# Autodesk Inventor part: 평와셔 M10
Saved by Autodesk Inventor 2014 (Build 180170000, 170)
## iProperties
Created: 2026-03
Part Number: 평와셔 M10
Material: 일반
Document SubType Name: Modeling
Designer: dg
Density: 1 g/cm^3
Appearance: 기본값
Author: dg
Author: jhkim
Description: 평면 와셔
Creation Date: 2025-06-27
Sending System: Autodesk Inventor 2026
Preprocessor: ST-DEVELOPER v20.1
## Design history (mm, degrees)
node "평와셔 M101"
body "Solid1"
node "기준1"
